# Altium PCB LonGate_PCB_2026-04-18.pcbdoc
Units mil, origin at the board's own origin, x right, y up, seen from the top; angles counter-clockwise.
Board outline 5018.1 x 4750 mil, 2 copper layers (Top Layer, Bottom Layer); 82 components, 100 nets, 301 pads, 185 vias.
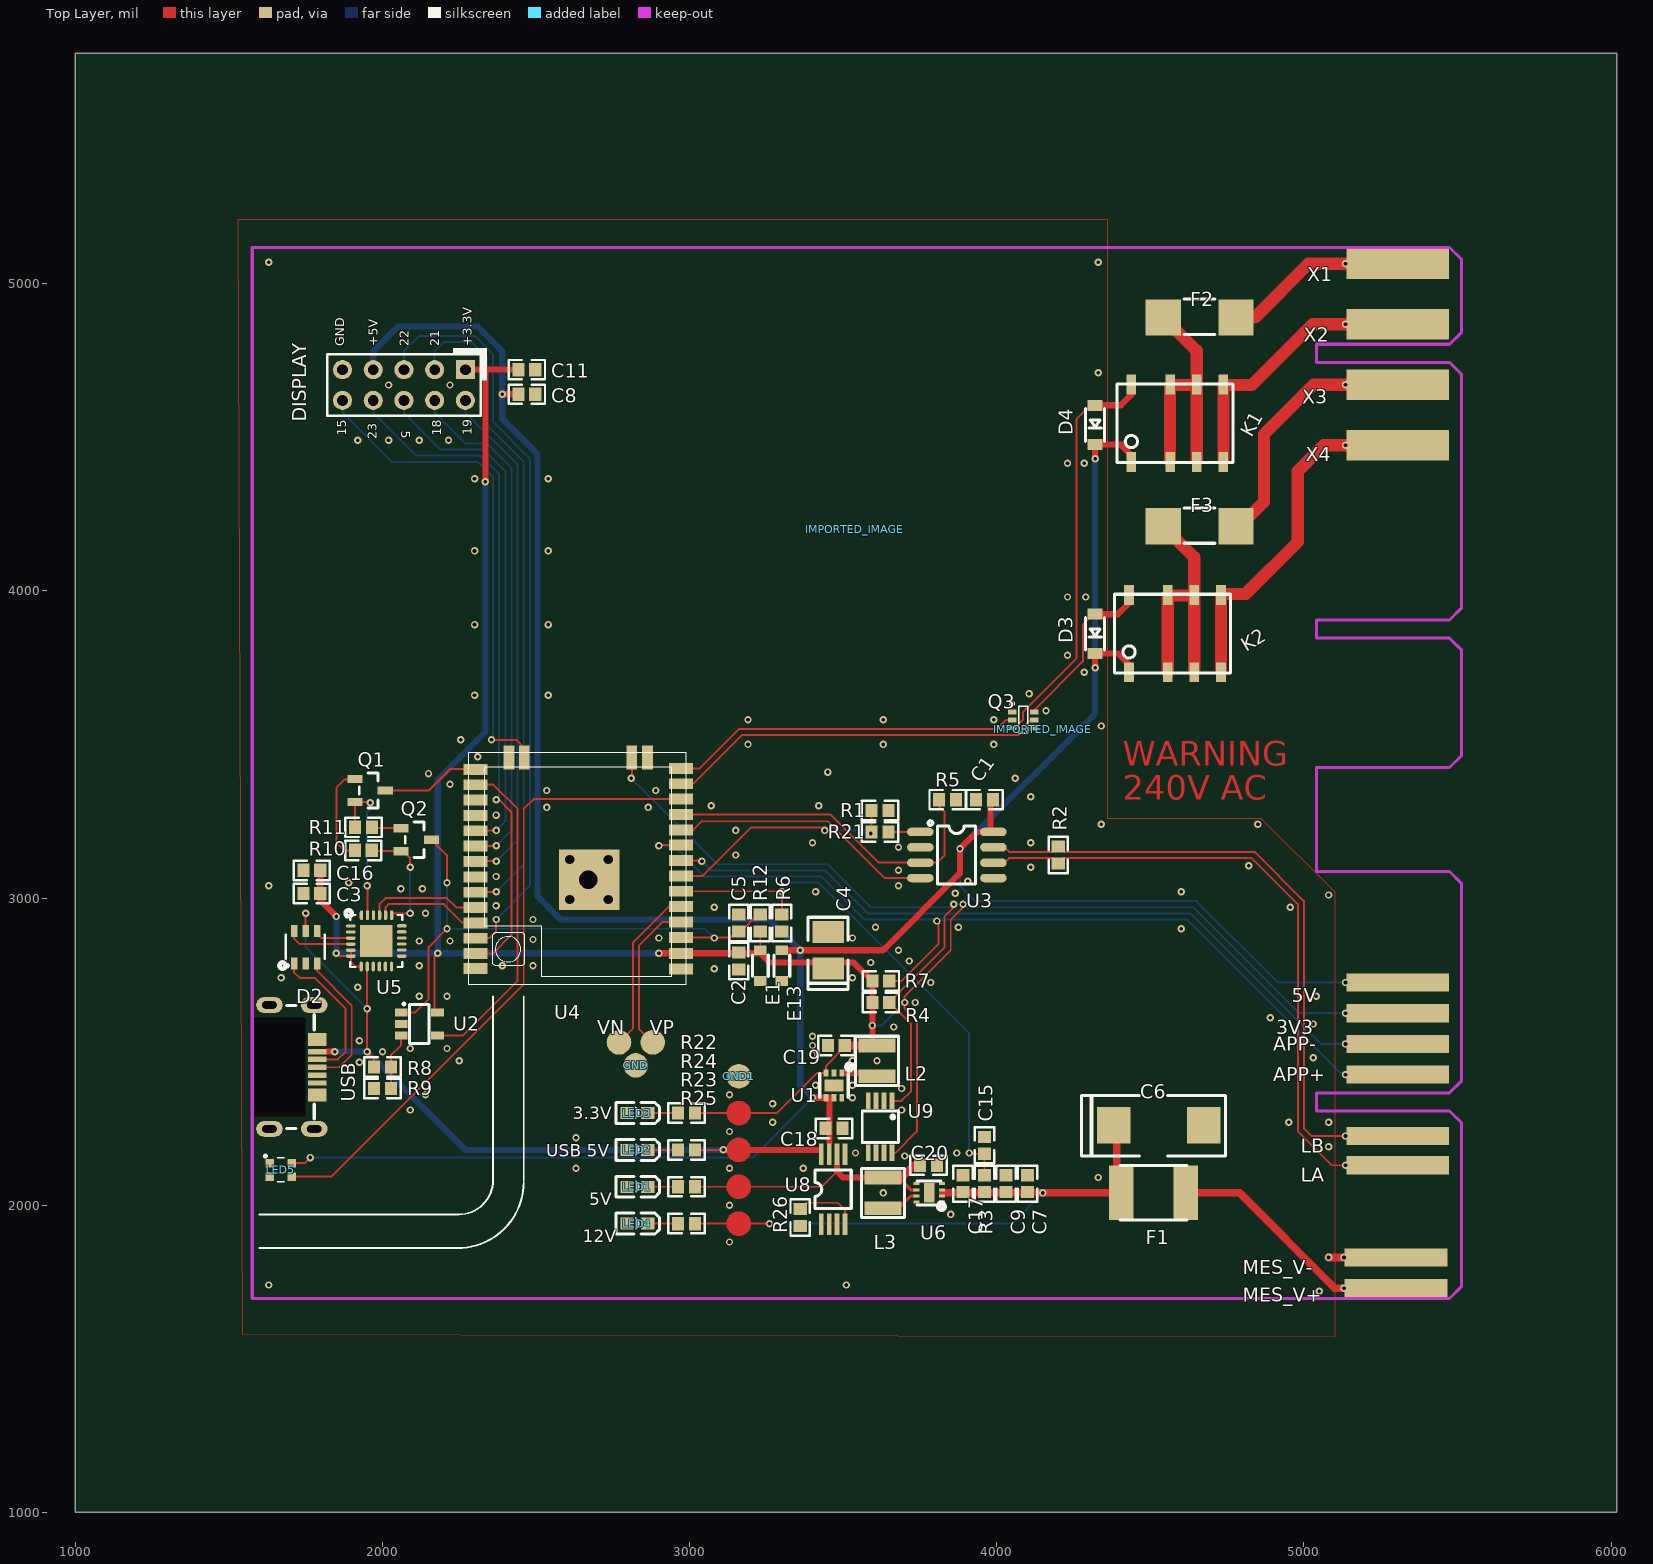
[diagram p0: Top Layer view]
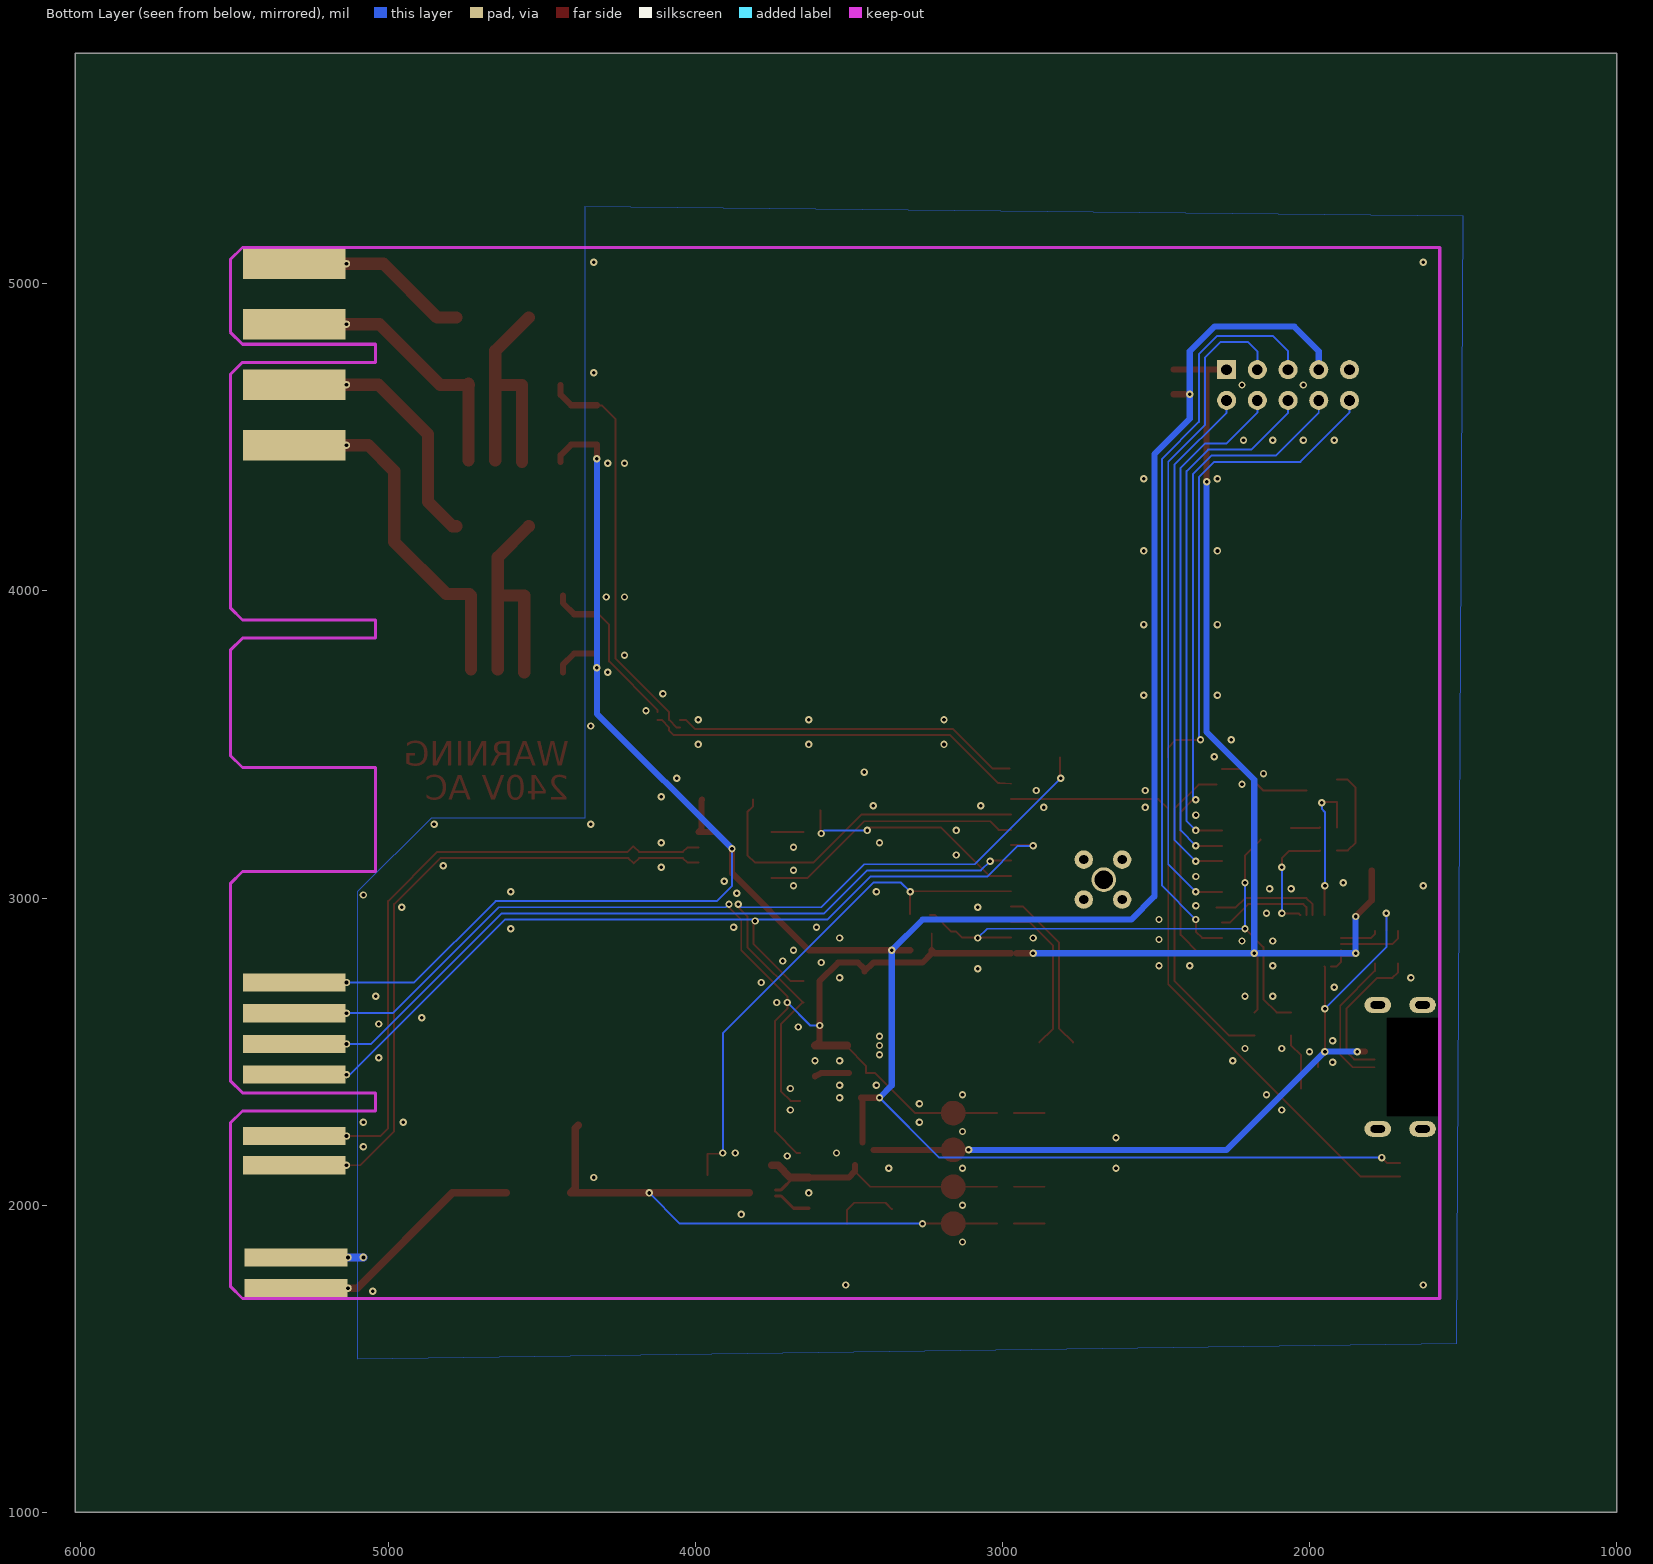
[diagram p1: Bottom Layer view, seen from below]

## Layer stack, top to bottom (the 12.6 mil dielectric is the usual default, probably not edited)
Top Layer: signal copper (thickness not stored)
Dielectric: dielectric 12.6, FR-4, Dk 4.8
Bottom Layer: signal copper (thickness not stored)

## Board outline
6018.1,1000 1000,1000 1000,5750 6018.1,5750

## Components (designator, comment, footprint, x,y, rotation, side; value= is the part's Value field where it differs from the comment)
3V3 "Pad" PAD 5135,2625 r0 top
5V "Pad" PAD 5135,2725 r0 top
APP+ "Pad" PAD 5135,2425 r0 top
APP- "Pad" PAD 5135,2525 r0 top
C1 "100n" 0603#1 3960,3320 r180 top
C2 "10u" 0603#1 3160,2795 r270 top
C3 "10u" 0603#1 1770,3015 r0 top
C4 "220uF" CASE-B_3528 3450.9,2830 r270 top
C5 "1uF" 0603#2 3160,2950 r270 top
C6 "220uF" CAP-SMD_L7.3-W4.3 4527,2260 r0 top
C7 "100nF" 0603#1 4100,2070 r270 top
C8 "100n" 0603#1 2470,4640 r0 top
C9 "100nF" 0603#1 4030,2070 r270 top
C11 "10u" 0603#1 2470,4720 r0 top
C15 "100n" 0603#1 3960,2195 r90 top
C16 "100n" 0603#1 1770,3090 r180 top
C17 "10u" 0603#1 3890,2070.01 r90 top
C18 "10u" 0603#1 3470,2250 r0 top
C19 "10u" 0603#2 3446.06,2520 r0 top
C20 "10u" 0603#2 3809.05,2130 r180 top
D2 "USBLC6-2SC6" SOT-23-6 1750,2840 r90 top
D3 "SS0520" SOD-123 4320,3860 r90 top
D4 "SS0520" SOD-123 4320,4540 r90 top
DISPLAY "Header" HDR-5X2/2.54 2070,4670 r180 top
E1 "UDD32C05L01" SOD-323-BI 3230,2780 r270 top
E13 "UDD32C05L01" SOD-323-BI 3300,2780 r90 top
F1 "2016L150DR" F-SMD2016 4510,2040 r180 top
F2 "SCT1.0A" F-SMD-6.1X2.6 4660,4890 r0 top
F3 "SCT1.0A" F-SMD-6.1X2.6 4660,4210 r0 top
GND "Pad" ROUND_PAD 2825,2455 r0 top
GND1 "Pad" ROUND_PAD 3160,2420 r0 top
IMPORTED_IMAGE "IMPORTED_IMAGE" IMPORTED_IMAGE 3537.17,4200 r0 top
IMPORTED_IMAGE "IMPORTED_IMAGE" IMPORTED_IMAGE 4150,3550.01 r0 top
K1 "HFD4/5-S" HFD4/5-S1R 4587.7,4546 r0 top
K2 "HFD4/3-S" HFD4/5-S1R 4580.01,3861 r0 top
L2 "2.2u" LPS3015-223MRB 3610,2470 r90 top
L3 "2.2u" LPS3015-223MRB 3630,2040 r90 top
LA "Pad" PAD 5135,2130 r0 top
LB "Pad" PAD 5135,2225 r0 top
LED1 "LED green" LED-0603F 2830,2060 r180 top
LED2 "LED blue" LED-0603F 2830,2180 r180 top
LED3 "LED red" LED-0603F 2830,2300 r180 top
LED4 "LED orange" LED-0603F 2830,1940 r180 top
LED5 "STATUS" LED_WS2812-2020_FL 1670,2130 r180 top
MES_V+ "Pad" PAD 5130,1730 r0 top
MES_V- "Y14" PAD 5130,1830 r0 top
Q1 "MMBT2222A" SOT-23(SOT-23-3) 2010,3350 r270 top
Q2 "MMBT2222A" SOT-23(SOT-23-3) 2160,3190 r270 top
Q3 "MUN5233DW1T1G" SOT-363 4086,3579.8 r270 top
R1 "2k2" 0603#1 3620,3285 r0 top
R2 "1k" 0603#1 4200,3140 r90 top
R3 "8k2" 0603#1 3960,2070 r270 top
R4 "2k2" 0603#1 3622.44,2660 r180 top
R5 "10k" 0603#1 3840,3320 r180 top
R6 "2k2" 0603#1 3300,2918.5 r90 top
R7 "1k" 0603#1 3622.44,2730 r180 top
R8 "1k" 0603#1 2000,2450 r0 top
R9 "2k2" 0603#1 2000,2380 r0 top
R10 "10k" 0603#2 1906.06,3155 r0 top
R11 "10k" 0603#2 1970,3230 r180 top
R12 "10k" 0603#2 3230,2950 r270 top
R21 "1k" 0603#1 3620,3215 r180 top
R22 "1k" 0603#1 2990,2300 r0 top
R23 "1k" 0603#1 2990,2060 r0 top
R24 "1k" 0603#1 2990,2180 r0 top
R25 "10k" 0603#1 2990,1940 r0 top
R26 "250" 0603#1 3360,1960 r270 top
U1 "TPS62291DRVR" SON-6-EP-2X2MM 3469.6,2390 r270 top
U2 "STWD100NYWY3F" SOT-23-5 2120,2590 r0 top
U3 "MAX1487CSA+T" SOIC-8_150MIL 3870,3140 r0 top
U4 "ESP32-WROOM/WROVER" ESP32-WROOM-32U 3090,2670 r180 top
U5 "CP2104-F03-GM" QFN-24_4X4X05P 1905,2905 r0 top
U6 "TPS62163DSG" WSON-8-PAD 3780,2040 r90 top
U8 "TPS2113APWR" TSSOP-8 3467,2052 r90 top
U9 "DS18B20U+T&R" USOP-8 3620,2255 r180 top
USB "MICRO_USB" MICRO_5P_C40940 1710,2450 r270 top
VN "Pad" ROUND_PAD 2770,2530 r0 top
VP "Pad" ROUND_PAD 2880,2530 r0 top
X1 "Pad" PAD-2.54 5135,5065 r0 top
X2 "Pad" PAD-2.54 5135,4868 r0 top
X3 "Pad" PAD-2.54 5135,4671 r0 top
X4 "Pad" PAD-2.54 5135,4474 r0 top

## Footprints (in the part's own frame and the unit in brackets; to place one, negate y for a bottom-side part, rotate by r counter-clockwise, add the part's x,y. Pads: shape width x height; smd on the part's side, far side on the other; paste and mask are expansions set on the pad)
0603#1 [mm]
  rect 1x1.1 smd paste+0 mask+0.102: 1(-0.7,0) 2(0.7,0)
  silkscreen extent -1.5,-0.8 1.5,0.8
0603#2 [mm]
  rect 1x1.1 smd paste+0 mask+0.102: 1(0.1,0) 2(1.5,0)
  silkscreen extent -0.7,-0.8 2.3,0.8
CAP-SMD_L7.3-W4.3 [mil]
  rect 110.2x118.5 smd paste+0 mask+4: 1(-146.5,0) 2(146.5,0)
  silkscreen extent -252,-100 218,97
CASE-B_3528 [mm]
  rect 1.8x2.6 smd paste+0 mask+0.102: 1(1.501,0) 2(-1.501,0)
  silkscreen extent -2.73,-1.65 3.26,1.65
ESP32-WROOM-32U [mm]
  rect 2x0.9 smd paste+0 mask+0.102: 1(3,-2.5) 2(3,-3.8) 3(3.002,-5.102) 4(3,-6.4) 5(3,-7.67) 6(3,-8.94) 7(3,-10.21) 8(3,-11.48) 9(3,-12.75) 10(3,-14.02) 11(3,-15.29) 12(3,-16.56) 13(3,-17.83) 14(3,-19.1) 25(20.002,-19.022) 26(20.002,-17.752) 27(20.002,-16.482) 28(20.002,-15.212) 29(20.002,-13.942) 30(20.002,-12.672) 31(20.002,-11.402) 32(20.002,-10.132) 33(20.001,-8.862) 34(20.002,-7.592) 35(20.002,-6.322) 36(20.002,-5.052) 37(20.002,-3.782) 38(20,-2.54)
  rect 0.9x2 smd paste+0 mask+0.102: 15(5.772,-20.001) 16(7.069,-20.001) 23(15.959,-20.001) 24(17.229,-20.001)
  rect 5x5 smd paste+0 mask+0.102: 39(10.602,-9.901)
  silkscreen extent 2.56,-20.4 20.56,-1.2
F-SMD2016 [mm]
  rect 2x4.5 smd paste+0 mask+0.102: 1(-2.667,0) 2(2.667,0)
  silkscreen extent -2.75,-2.25 2.75,2.25
F-SMD-6.1X2.6 [mm]
  rect 2.9x3 smd paste+0 mask+0.102: 1(-3,0) 2(3,0)
  silkscreen extent -1.27,-1.4 1.27,1.52
HDR-5X2/2.54 [mil]
  rect 62x62 hole 35 paste+0 mask+4: 1(-200,-50)
  round 62 hole 35 paste+0 mask+4: 2(-200,50) 3(-100,-50) 4(-100,50) 5(0,-50) 6(0,50) 7(100,-50) 8(100,50) 9(200,-50) 10(200,50)
  silkscreen extent -250,-100 250,100
HFD4/5-S1R [mm]
  rect 0.8x1.65 smd paste+0 mask+0.102: 1(-3.8,-3.2) 2(-0.6,-3.2) 3(1.6,-3.2) 4(3.8,-3.2) 5(3.8,3.2) 6(1.6,3.2) 7(-0.6,3.2) 8(-3.8,3.2)
  silkscreen extent -5,-3.25 4.6,3.25
IMPORTED_IMAGE [mil]
LED-0603F [mil]
  rect 43x39 smd paste+0 mask+4: 1(-33.5,0) 2(33.5,0)
  silkscreen extent -72,-34 70,34
LED_WS2812-2020_FL [mil]
  rect 27.56x27.56 smd paste+0 mask+4: 1(36.92,-6.66) 2(36.92,36.65) 3(-35.13,36.65) 4(-35.13,-6.66)
  silkscreen extent -11,-34 55,54
LPS3015-223MRB [mil]
  rect 44.9x120.1 smd paste+0 mask+4: P$1(-50,0) P$2(50,0)
  silkscreen extent -80,-70 80,70
MICRO_5P_C40940 [mm]
  rect 0.45x1.5 smd paste+0 mask+0.102: 1(-1.276,1.975) 2(-0.626,1.975) 3(0.025,1.975) 4(0.675,1.975) 5(1.325,1.975)
  oval 1.3x2.2 hole 0.6 slot 1.2 at 90 deg paste+0 mask+0.102: 5(-5.125,1.725) 5(-5.125,-1.975) 5(5.125,1.725) 5(5.125,-1.975)
  rect 1.1x1.5 smd paste+0 mask+0.102: ""(-2.275,1.975) ""(2.325,1.975)
  Multi-Layer board cut-out: -4.064,0.963 4.064,0.963 4.064,-3.355 -4.064,-3.355
  silkscreen extent -5.08,-0.56 5.08,1.73
PAD [mm]
  round 0.61 hole 0.305 paste+0 mask+0.102: 1(0,0)
  rect 8.5x1.5 smd far side paste+0 mask+0.102: 1(4.318,0)
  rect 8.5x1.5 smd paste+0 mask+0.102: 1(4.318,0)
PAD-2.54 [mm]
  round 0.61 hole 0.305 paste+0 mask+0.102: 1(0,0)
  rect 8.5x2.54 smd far side paste+0 mask+0.102: 1(4.318,0)
  rect 8.5x2.54 smd paste+0 mask+0.102: 1(4.318,0)
QFN-24_4X4X05P [mm]
  oval 0.8x0.28 smd paste+0 mask+0.102: 1(-0.203,0.102) 2(-0.203,-0.399) 3(-0.203,-0.899) 4(-0.203,-1.397) 5(-0.203,-1.897) 6(-0.203,-2.398) 13(4.013,-2.388) 14(4.013,-1.887) 15(4.013,-1.387) 16(4.013,-0.889) 17(4.013,-0.389) 18(4.013,0.112)
  oval 0.28x0.8 smd paste+0 mask+0.102: 7(0.66,-3.251) 8(1.161,-3.251) 9(1.661,-3.251) 10(2.159,-3.251) 11(2.659,-3.251) 12(3.16,-3.251) 19(3.175,0.991) 20(2.675,0.991) 21(2.174,0.991) 22(1.676,0.991) 23(1.176,0.991) 24(0.676,0.991)
  rect 2.68x2.68 smd paste+0 mask+0.102: 25(1.905,-1.143)
  silkscreen extent -0.57,-3.29 4.06,1.01
ROUND_PAD [mil]
  round 80 smd paste+0 mask+4: 1(0,0)
SOD-123 [mil]
  rect 35.8x48 smd paste+0 mask+4: 1(64,0) 2(-64,0)
  silkscreen extent -53,-31 53,31
SOD-323-BI [mm]
  rect 0.8x1 smd paste+0 mask+0.102: 1(-1.27,0) 2(1.27,0)
  silkscreen extent -0.89,-0.66 0.89,0.66
SOIC-8_150MIL [mm]
  oval 2.2x0.7 smd paste+0 mask+0.102: 1(-3.023,1.905) 2(-3.023,0.635) 3(-3.023,-0.635) 4(-3.023,-1.905) 5(3.023,-1.905) 6(3.023,-0.635) 7(3.023,0.635) 8(3.023,1.905)
  silkscreen extent -2.37,-2.41 1.55,2.83
SON-6-EP-2X2MM [mm]
  rect 0.6x0.4 smd paste+0 mask+0.102: 1(-1.016,0.65) 2(-1.016,0) 3(-1.016,-0.65) 4(1.016,-0.65) 5(1.016,0) 6(1.016,0.65)
  rect 1x1.6 smd paste+0 mask+0.102: 7(0,0.01)
  silkscreen extent -1.62,-1.17 1,1.33
SOT-23(SOT-23-3) [mm]
  rect 0.7x1.25 smd paste+0 mask+0.102: 1(-0.95,-2.52) 2(0.95,-2.52) 3(0,-0.02)
  silkscreen extent -1.46,-2.17 1.46,-0.62
SOT-23-5 [mm]
  rect 1.06x0.65 smd paste+0 mask+0.102: 1(-1.5,0.95) 2(-1.5,0) 3(-1.5,-0.95) 4(1.5,-0.95) 5(1.5,0.95)
  silkscreen extent -1.33,-1.6 0.8,1.71
SOT-23-6 [mm]
  rect 1x0.55 smd paste+0 mask+0.102: 1(-1.35,0.95) 2(-1.35,0) 3(-1.35,-0.95) 4(1.35,-0.95) 5(1.35,0) 6(1.35,0.95)
  silkscreen extent -1.67,-1.56 1.01,1.67
SOT-363 [mil]
  rect 15.75x27.6 smd paste+0 mask+4: 1(-25.8,-36) 2(-0.2,-36) 3(25.4,-36) 4(25.8,36) 5(0.2,36) 6(-25.4,36)
  silkscreen extent -58,-42 44,15
TSSOP-8 [mil]
  rect 71x16 smd paste+0 mask+4: 1(-114,38.5) 2(-114,12.5) 3(-114,-12.5) 4(-114,-38.5) 5(114,-38.5) 6(114,-12.5) 7(114,12.5) 8(114,38.5)
  silkscreen extent -63,-59 63,60
USOP-8 [mm]
  rect 0.4x1.349 smd paste+0 mask+0.102: 1(-0.975,-2.15) 2(-0.325,-2.152) 3(0.325,-2.151) 4(0.975,-2.152) 5(0.976,2.149) 6(0.324,2.152) 7(-0.324,2.149) 8(-0.976,2.152)
  silkscreen extent -1.52,-1.3 1.48,1.3
WSON-8-PAD [mil]
  rect 10x19.7 smd paste+0 mask+4: 1(-30,-41) 2(-10,-41) 3(10,-41) 4(30,-41) 5(30,41) 6(10,41) 7(-10,41) 8(-30,41)
  rect 63x35.4 smd paste+0 mask+4: 9(0,0)
  silkscreen extent -49,-49 39,39

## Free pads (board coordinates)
  round 60 hole 30 paste+0 mask+4: 1(2610,2995) 1(2610,3125) 1(2735,2995) 1(2735,3125)
  round 80 hole 60 paste+0 mask+4: 1(2670,3060)

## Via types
v1: diameter 24, hole 12, Top Layer to Bottom Layer, tented both sides, 143 vias
v2: diameter 24.02, hole 12.2, Top Layer to Bottom Layer, tented both sides, 42 vias

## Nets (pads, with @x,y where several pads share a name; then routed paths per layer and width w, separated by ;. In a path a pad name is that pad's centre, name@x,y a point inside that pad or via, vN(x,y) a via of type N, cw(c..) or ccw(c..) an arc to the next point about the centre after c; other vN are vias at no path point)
+5V: C20.2 L3.P$2 R23.2 U6.6 U8.6 | length 1049.2
  Top Layer w6.3: R23.2 3430,2060 3480,2110
  Top Layer w10: L3.P$2@3625,2090 3680,2090 3720,2050 U6.6
  Top Layer w20: 3480,2130 3480,2110 3500,2090 L3.P$2@3625,2090
  Top Layer w25: L3.P$2 3690,2090 3730,2130 C20.2
  Top Layer w40: 3180,2060 ccw(c3160,2060) 3180,2060
ADC: C15.1 R3.1 R6.2 U4.6 | length 1737.7
  Top Layer w6.3: U4.6 3298.03,3021.97 v1(3300,3020) R6.2@3300,2947.55 ; v1(3910,2170) 3912.56,2167.44 C15.1 R3.1
  Bottom Layer w6.3: v1(3300,3020) 3330,3050 3420,3050 3910,2560 v1(3910,2170)
APP+: APP+.1 R7.1 U4.9 | length 2905.5
  Top Layer w6.3: v1(2900,3170) 2901.97,3171.97 U4.9 ; R7.1@3647.6,2730 3690,2730 3810,2850 3810,2920 v1(3805,2925)
  Bottom Layer w6.3: v1(2900,3170) 2950,3170 3050,3070 3430,3070 3570,2930 4620,2930 5125,2425 APP+.1@5135,2425
APP-: APP-.1 U4.8 | length 2410.4
  Top Layer w6.3: U4.8 3038.03,3121.97 v1(3040,3120)
  Bottom Layer w6.3: v1(3040,3120) 3070,3090 3440,3090 3580,2950 4630,2950 5055,2525 APP-.1@5135,2525
D+: D2.3 USB.3 | length 472.6
  Top Layer w6.3: D2.3 1787.4,2762.6 1900,2650 1900,2490 1859.01,2449.01 USB.3
D+P: D2.4 U5.3 | length 125.5
  Top Layer w6.3: D2.4 1787.4,2882.6 1800.4,2869.6 U5.3
D-: D2.1 USB.2 | length 488.2
  Top Layer w6.3: D2.1 1712.6,2757.4 1730,2740 1780,2740 1880,2640 1880,2500 1854.63,2474.63 USB.2
D-P: D2.6 U5.4 | length 217.3
  Top Layer w6.3: D2.6 1712.6,2867.4 1730,2850 U5.4
DISP_2: DISPLAY.2 U4.31 | length 1683.7
  Top Layer w6.3: U4.31@2285.67,3120 v1(2370,3120)
  Bottom Layer w6.3: DISPLAY.2 2270,4580 2440,4410 2440,3190 v1(2370,3120)
DISP_3: DISPLAY.3 U4.33 | length 2174.5
  Top Layer w6.3: U4.33@2285.67,3020 v1(2370,3020)
  Bottom Layer w6.3: DISPLAY.3 2170,4780 2200,4810 2290,4810 2340,4760 2340,4540 2460,4420 2460,3110 v1(2370,3020)
DISP_4: DISPLAY.4 U4.30 | length 1699.6
  Top Layer w6.3: U4.30@2285.7,3170 v1(2370,3170)
  Bottom Layer w6.3: DISPLAY.4 2170,4580 2270,4480 2340,4480 2420,4400 2420,3220 v1(2370,3170)
DISP_5: DISPLAY.5 U4.36 | length 2463.4
  Top Layer w6.3: U4.36@2285.7,2870 2350,2870 2370,2890 v1(2370,2930)
  Bottom Layer w6.3: DISPLAY.5 2070,4780 2120,4830 2300,4830 2360,4770 2360,4550 2480,4430 2480,3040 v1(2370,2930)
DISP_6: DISPLAY.6 U4.29 | length 1715.5
  Top Layer w6.3: U4.29@2285.67,3220 v1(2370,3220)
  Bottom Layer w6.3: DISPLAY.6 2070,4580 2190,4460 2330,4460 2400,4390 2400,3250 v1(2370,3220)
DISP_8: DISPLAY.8 U4.37 | length 2206.4
  Top Layer w6.3: U4.37 2358.9,2818.9 2420,2880 2420,3280 2380,3320 v1(2370,3320)
  Bottom Layer w6.3: DISPLAY.8 1970,4580 2110,4440 2320,4440 2380,4380 2380,3330 v1(2370,3320)
DISP_10: DISPLAY.10 U4.23 | length 1622.7
  Top Layer w6.3: v1(2355,3515) 2435,3515 2461.7,3488.3 U4.23
  Bottom Layer w6.3: DISPLAY.10 1870,4580 2030,4420 2310,4420 2360,4370 2360,3520 v1(2355,3515)
DTR: Q1.2 R11.2 U5.23 | length 503.4
  Top Layer w6.3: Q1.2 Q1.2@1910.95,3312.45 ; R11.2@1910.95,3230 Q1.2@1910.95,3312.45 ; v1(1950,3040) 1951.3,3038.7 U5.23 ; v1(1960,3310) 1957.55,3312.45 Q1.2@1910.95,3312.45
  Bottom Layer w6.3: v1(1950,3040) 1950,3280 1960,3290 v1(1960,3310)
GND: C1.2 C2.2 C3.1 C4.2 C5.1 C6.2 C7.1 C8.2 C9.1 C11.2 C15.2 C16.2 C17.2 C18.2 C19.1 C20.1 D2.2 DISPLAY.9 E1.2 E13.1 GND1.1 GND.1 LED1.2 LED2.2 LED3.2 LED4.2 LED5.2 MES_V-.1 pad.1 Q3.1 Q3.4 R1.2 R5.1 R6.1 R9.1 R26.2 U1.2 U1.6 U1.7 U2.2 U3.2 U3.5 U4.1 U4.15 U4.24 U4.38 U4.39 U5.2 U6.1 U6.4 U6.5 U6.9 U8.2 U8.3 U8.5 U9.4 USB.5 | length 100
  Top Layer w25: v1(5080,1830) MES_V-.1@5130,1830
  Bottom Layer w25: v1(5080,1830) MES_V-.1@5130,1830
  other v1: 5050,1720 1630,1740 3510,1740 3130,1880 3850,1970 3130,2000 3630,2040 4330,2090 2630,2120 3130,2120 3370,2120 3700,2160 3540,2170 3870,2170 5080,2190 2630,2220 3130,2240 3270,2270 4950,2270 5080,2270 2090,2310 3690,2310 3270,2330 3530,2350 2140,2360 3130,2360 3690,2380 3410,2390 3530,2390 1925,2465 3530,2470 3610,2470 5030,2480 3400,2490 2000,2500 2090,2510 2210,2510 3400,2520 1925,2535 3400,2550 3665,2580 5030,2590 4890,2610 3735,2660 2120,2680 5040,2680 1920,2710 3785,2725 1670,2740 3530,2740 3080,2770 2120,2780 2390,2780 2490,2780 3590,2790 3715,2795 3680,2830 2900,2870 3530,2870 4600,2900 3605,2905 3875,2905 3080,2970 4955,2970 5080,3010 3865,3015 4600,3020 1630,3040 3905,3055 4110,3100 4820,3105 3150,3140 3400,3180 4110,3180 3150,3220 4340,3240 4850,3240 4110,3330 4060,3390 3450,3410 3190,3500 3630,3500 3990,3500 4340,3560 3190,3580 3630,3580 3990,3580 4160,3610 4105,3665 4285,3735 4230,3790 4230,3980 4290,3980 4230,4415 4285,4415 4330,4710 1630,5070 4330,5070
  other v2: 2250,2470 2210,2680 2120,2860 2220,2860 2490,2865 2490,2930 2140,2950 2370,2975 3410,3020 2060,3030 2130,3030 3680,3040 1890,3050 2370,3070 3680,3090 3680,3165 2370,3270 2535,3295 2865,3295 3070,3300 3420,3300 2535,3350 2890,3350 2220,3370 2150,3405 2310,3460 2255,3515 2300,3660 2540,3660 2300,3890 2540,3890 2300,4130 2540,4130 2300,4365 2540,4365 1920,4490 2020,4490 2120,4490 2215,4490 2020,4670 2220,4670
IO0: Q1.3 U4.25 | length 305.5
  Top Layer w6.3: Q1.3 2150,3350 2220,3420 U4.25@2285.7,3420
K1_2: F2.1 K1.2 K1.3 K1.6 K1.7 | length 851.7
  Top Layer w40: F2.1 4650.7,4781.19 4650.7,4670 4564.09,4670 K1.2 ; K1.3@4651.1,4425 K1.6@4651.1,4675
K1_4: K1.4 K1.5 X2.1 | length 729.7
  Top Layer w40: K1.5@4737.32,4670 4830,4670 5028,4868 X2.1@5135,4868 ; K1.4@4737.71,4425 K1.5@4737.71,4675
K1_8: D4.1 K1.8 Q3.3 | length 1340.4
  Top Layer w6.3: Q3.3 4059.4,3554.4 4085,3580 4085,3605 4260,3780 4260,4560 4304,4604 D4.1
  Top Layer w20: D4.1 4404,4604 4438.1,4638.1 K1.8@4438.1,4670
K2_2: F3.1 K2.2 K2.3 K2.6 K2.7 | length 843.5
  Top Layer w40: F3.1 4642.99,4108.9 K2.6@4642.99,3985 ; K2.2 4556.38,3985 K2.6@4642.99,3985 ; K2.3@4642.99,3745 K2.6@4642.99,3985
K2_4: K2.4 K2.5 X4.1 | length 1145.6
  Top Layer w40: K2.4@4729.6,3745 K2.5@4729.6,3985 ; K2.5@4734.6,3990 4810,3990 4980,4160 4980,4390 5064,4474 X4.1@5305,4474
K2_8: D3.1 K2.8 Q3.6 | length 554.4
  Top Layer w6.3: Q3.6 4122,3612 4280,3770 4280,3890 4314,3924 D3.1
  Top Layer w20: D3.1 4394,3924 4430.4,3960.4 K2.8@4430.4,3985
L2_P$1: L2.P$1 U1.1 | length 112.4
  Top Layer w20: U1.1@3500,2430 3590,2430 L2.P$1
LED1_1: LED1.1 R23.1 | length 98.9
  Top Layer w6.3: LED1.1 R23.1
LED2_1: LED2.1 R24.1 | length 98.9
  Top Layer w6.3: LED2.1 R24.1
LED3_1: LED3.1 R22.1 | length 98.9
  Top Layer w6.3: LED3.1 R22.1
LED5_1: LED5.1
LON_DE: R5.2 U3.3 U4.11 | length 1120.7
  Top Layer w6.3: U4.11 3458.03,3271.97 3615,3115 U3.3 3805,3115 3830,3140 3830,3280 3812.5,3297.5 R5.2@3812.5,3320
LON_DI: U3.4 U4.10 | length 867.3
  Top Layer w6.3: U4.10 3012,3222 3040,3250 3450,3250 3635,3065 U3.4
LON_RO: R1.1 R21.2 U4.7 | length 761.8
  Top Layer w6.3: U4.7 3042,3072 3200,3230 3430,3230 v1(3440,3220) ; R21.2@3592.45,3215 R1.1@3592.45,3284.99
  Bottom Layer w6.3: v1(3440,3220) 3580,3220 v1(3590,3210)
R2_1: LA.1 R2.1 U3.6 | length 2014.5
  Top Layer w6.3: U3.6 4025,3115 4040,3130 4182.44,3130 R2.1 ; R2.1 4217.6,3130 4830,3130 4980,2980 4980,2240 5090,2130 LA.1@5135,2130
R2_2: LB.1 R2.2 U3.7 | length 1983.4
  Top Layer w6.3: U3.7 4025,3165 4040,3150 4182.45,3150 R2.2 ; R2.2@4200,3167.5 4202.5,3167.5 4220,3150 4840,3150 5000,2990 5000,2250 5025,2225 LB.1@5135,2225
R10_1: Q1.1 R10.1 | length 322.4
  Top Layer w6.3: R10.1@1909.6,3153.8 R10.1 1875,3155 1850,3180 1850,3359.2 1877,3386.2 Q1.1@1910.4,3386.2
R11_1: Q2.1 R11.1 | length 95.8
  Top Layer w6.3: R11.1 1968.66,3227.4 Q2.1
R25_1: LED4.1 R25.1 | length 98.9
  Top Layer w6.3: LED4.1 R25.1
REL1: Q3.5 U4.13 | length 1250.7
  Top Layer w6.3: U4.13 3010,3375 3015,3375 3170,3530 4070,3530 4085,3545 4085,3555 4109.6,3579.6 Q3.5 Q3.5@4112.1,3579.6
REL2: Q3.2 U4.14 | length 1139.9
  Top Layer w6.3: U4.14@2976,3421 3031,3421 3160,3550 4000,3550 4030,3580 Q3.2
RESET: C5.2 Q2.3 R12.1 U2.1 U4.3 | length 1848.9
  Top Layer w6.3: U2.1@2061,2627.4 2107.4,2627.4 2150,2670 2150,2840 v1(2210,2900) ; Q2.3 2210,3139.2 v1(2210,3050) ; U4.3 3130.8,2870.8 3150.9,2890.9 C5.2 3165.9,2890.9 3220,2945 R12.1@3235,2945
  Bottom Layer w6.3: v1(2210,3050) v1(2210,2900) 3050,2900 v1(3080,2870)
RTS: Q2.2 R10.2 U5.19 | length 377.7
  Top Layer w6.3: R10.2 1967.52,3152.6 Q2.2 2067.4,3152.6 2090,3130 v1(2090,3100) ; U5.19 2036,2950 v2(2090,2950)
  Bottom Layer w6.3: v2(2090,2950) v1(2090,3100)
RXD0: U4.34 U5.21 | length 369.4
  Top Layer w6.3: U5.21 1990.6,2980.6 2010,3000 2210,3000 2241.1,2968.9 U4.34
S$11: 
S$21: 
S$23: 
S$27: 
S$30: 
S$32: 
S$67: 
S$69: 
S$110: 
S$112: 
S$114: 
S$116: 
S$282: 
S$289: 
S$1042: 
S$1047: 
TEMP_INT: R4.1 U4.16 U9.1 | length 2104.6
  Top Layer w6.3: v1(2810,3390) 2811.7,3388.3 U4.16 ; U9.1@3658.4,2339.7 3689.7,2339.7 3720,2370 3720,2590 R4.1 ; v1(3860,2980) 3860,2970 3830,2940 3830,2840 R4.1 ; R4.1 3647.6,2660 R4.1
  Bottom Layer w6.3: v1(2810,3390) 3090,3110 3450,3110 3590,2970 3850,2970 v1(3860,2980)
TXD0: U4.35 U5.20 | length 330.6
  Top Layer w6.3: U5.20 2010.3,2970.3 2020,2980 2200,2980 2260,2920 U4.35@2285.7,2920
U2_3: R8.2 R9.2 U2.3 | length 186.4
  Top Layer w6.3: R9.2 2027.56,2487.56 2060.95,2520.95 U2.3@2060.95,2552.6
U3_1: R21.1 U3.1 | length 103.4
  Top Layer w6.3: R21.1 3675,3215 U3.1
U4_4: U4.4 VP.1 | length 502.4
  Top Layer w6.3: VP.1 2835,2575 2835,2845 2912,2922 U4.4
U4_5: U4.5 VN.1 | length 549
  Top Layer w6.3: VN.1 2815,2575 2815,2855 2932,2972 U4.5
U4_27: U4.27
U4_28: U4.28
U4_32: U4.32
U5_1: U5.1
U5_9: U5.9
U5_10: U5.10
U5_11: U5.11
U5_12: U5.12
U5_13: U5.13
U5_14: U5.14
U5_15: U5.15
U5_16: U5.16
U5_17: U5.17
U5_18: U5.18
U5_22: U5.22
U5_24: U5.24
U5_25: U5.25
U6_7: L3.P$1 U6.7 | length 125.6
  Top Layer w10: L3.P$1 3680,1990 3720,2030 U6.7
U6_8: U6.8
U8_1: U8.1
U8_4: R26.1 U8.4 | length 210.2
  Top Layer w6.3: R26.1 3380.44,2008 3482,2008 3505.5,1984.5 U8.4
U9_2: U9.2
U9_3: U9.3
U9_5: U9.5
U9_6: U9.6
U9_7: U9.7
USB_4: USB.4
VCC: 3V3.1 C2.1 C3.2 C4.1 C11.1 C16.1 C19.2 DISPLAY.1 E1.1 L2.P$2 R4.2 R7.2 R12.2 R22.2 U1.3 U2.5 U4.2 U5.5 U5.6 U5.7 U9.8 | length 8185.7
  Top Layer w6.3: v1(1850,2820) 1859.4,2810.6 U5.6 ; U5.5 1897,2820.3 U5.6 ; U5.7 1913,2777 1897,2793 U5.6 ; U2.5 2170,2636.4 2170,2810 v1(2180,2820) ; R22.2 3284,2300 3414,2430 U1.3 3444,2454 3505.11,2515.11 C19.2 ; E1.1@3230,2835 R12.2@3230,2884.9 ; U9.8 3670.3,2170.3 3740,2240 3740,2600 3700,2640 v1(3700,2660) 3700,2680 3850,2830 3850,2930 3890,2970 v1(3890,2980)
  Top Layer w20: C16.1 1797.56,2992.44 v1(1850,2940) ; v1(2335,4355) 2335,4720 DISPLAY.1 C11.1 ; v1(2900,2820) U4.2@2954.33,2820 ; U4.2@2971.9,2820 3220,2820 E1.1 3230,2820 3260,2790 3420,2790 C4.1@3449.1,2760.9 ; C4.1 3470,2790 3534.9,2790 R7.2 3594.89,2535.11 L2.P$2
  Top Layer w25: C19.2 3537.2,2520 L2.P$2
  Top Layer w40: 3180,2300 ccw(c3160,2300) 3180,2300
  Bottom Layer w6.3: v1(3595,2585) 3625,2585 v1(3700,2660) ; v1(3890,2980) 3900,2970 4640,2970 4985,2625 3V3.1@5135,2625
  Bottom Layer w20: v1(1850,2940) v1(1850,2820) v1(2900,2820) ; v1(2180,2820) 2180,3385 2335,3540 v1(2335,4355)
VCC5: 5V.1 C1.1 C8.1 C18.1 D3.2 D4.2 DISPLAY.7 E13.2 K1.1 K2.1 LED5.4 U1.4 U1.5 U3.8 U8.7 | length 10193.7
  Top Layer w6.3: LED5.4 1746.7,2136.7 v1(1765,2155)
  Top Layer w20: v1(2390,4640) C8.1 ; E13.2 v1(3360,2830) 3630,2830 3880,3080 v1(3880,3160) 3935,3215 U3.8 3980,3224 3980,3317.56 C1.1@3977.56,3320 ; v1(3400,2350) 3460,2350 ; 3455,2204 3455,2350 ; v1(4320,3750) D3.2 4394,3796 4430.4,3759.6 K2.1 ; v1(4320,4430) D4.2 4404,4476 4438.1,4441.9 K1.1
  Bottom Layer w6.3: v1(1765,2155) 3205,2155 v1(3400,2350) ; v1(3880,3160) 3880,3040 3930,2990 4650,2990 4915,2725 5V.1@5135,2725
  Bottom Layer w20: DISPLAY.7 1970,4780 2050,4860 2310,4860 2390,4780 2390,4560 2505,4445 2505,3005 2580,2930 3260,2930 v1(3360,2830) 3360,2390 v1(3400,2350) ; v1(3880,3160) 4320,3600 v1(4320,3750) v1(4320,4430)
VIN: F1.1 MES_V+.1 | length 643.4
  Top Layer w25: F1.1 4790,2040 5100,1730 MES_V+.1@5130,1730
VIN_F: C6.1 C7.2 C9.2 C17.1 F1.2 R3.2 R25.2 U6.2 U6.3 | length 2109.7
  Top Layer w6.3: R25.2 v1(3260,1940)
  Top Layer w25: 3825,2040 3950,2040 F1.2 4390,2055 4390,2250.5 C6.1
  Top Layer w40: 3180,1940 ccw(c3160,1940) 3180,1940
  Bottom Layer w6.3: v1(3260,1940) 4050,1940 v1(4150,2040)
VUSB: D2.5 R8.1 R24.2 U5.8 U8.8 USB.1 | length 2736
  Top Layer w6.3: D2.5 v1(1750,2950) ; U5.8 1950,2776.3 v1(1950,2640) 1950,2500.23 1972.44,2477.79 R8.1 ; R24.2 v1(3110,2180)
  Top Layer w20: 1820,2500 v1(1845,2500) ; v1(3110,2180) 3419,2180
  Top Layer w40: 3180,2180 ccw(c3160,2180) 3180,2180
  Bottom Layer w6.3: v1(1750,2950) 1750,2840 v1(1950,2640)
  Bottom Layer w20: v1(1845,2500) 1949.77,2500 v1@1950,2500.23 ; v1(1950,2500) 2270,2180 v1(3110,2180)
WDT_WDI: U2.4 U4.26 | length 1064.7
  Top Layer w6.3: U2.4 2262.6,2552.6 2440,2730 2440,3290 2361.1,3368.9 U4.26
WS2812: LED5.3 U4.12 | length 2109.6
  Top Layer w6.3: LED5.3@1705.1,2093.3 1833.3,2093.3 2460,2720 2460,3290 2492,3322 U4.12
X1_1: F2.2 X1.1 | length 429.4
  Top Layer w40: F2.2 4840,4890 5015,5065 X1.1@5135,5065
X3_1: F3.2 X3.1 | length 846.7
  Top Layer w40: F3.2 4790,4210 4870,4290 4870,4510 5031,4671 X3.1@5305,4671
pads on no net: USB.

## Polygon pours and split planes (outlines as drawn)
GND on Bottom Layer (solid): 1500,5220 4360,5250 4360,3260 4860,3260 5100,3020 5100,1500 1520,1550 1500,5220
GND on Top Layer (solid): 1530,5210 2950,5210 4360,5210 4360,3260 4860,3260 5100,3020 5100,1570 1544.49,1578.52 1530,5210

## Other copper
Top Layer:
  pour cut-out net VUSB: 1570,2620 1760,2620 1760,2280 1570,2280
  text "WARNING" at 4410,3430 h80
  text "240V AC" at 4410,3320 h80
Bottom Layer:
  pour cut-out net VUSB: 1570,2620 1760,2620 1760,2280 1570,2280

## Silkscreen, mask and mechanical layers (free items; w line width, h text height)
Top Overlay:
  rectangle: 2320,4685 2340,4775
  rectangle: 2230,4770 2340,4790
  circle w15: c1890,2950 r10
  circle w15: c3520,2450 r10
  circle w15: c3820,1995 r10
  circle w15: c1675,2780 r10
  lines w6.3 net S$1042: 1600,1970 2250,1970 ; 2248.58,1969.99 ccw(c2248.58,2081.42) 2360.01,2081.42 ; 2360,2080 2360,2680
  lines w6.3 net S$1047: 1600,1860 2245,1860 ; 2244.09,1859.98 ccw(c2244.09,2075.91) 2460.02,2075.91 ; 2460,2080 2460,2680
  text "GND" at 1875.9,4796.72 h30 r90
  text "+5V" at 1985,4796.72 h30 r90
  text "22" at 2085,4796.72 h30 r90
  text "21" at 2185,4796.72 h30 r90
  text "+3.3V" at 2291.41,4796.72 h30 r90
  text "5" at 2061.41,4520.9 h30 r270
  text "19" at 2291.41,4506.48 h30 r90
  text "15" at 1881.41,4505.12 h30 r90
  text "18" at 2191.41,4505.12 h30 r90
  text "23" at 1981.41,4492.81 h30 r90
  text "3.3V" at 2620,2280 h40
  text "USB 5V" at 2532.7,2158.2 h40
  text "5V" at 2673.13,2000 h40
  text "12V" at 2652.03,1880 h40
Top Solder:
  rectangle: 1625,1975 1735,2025
  rectangle: 1625,1805 1735,1855
  rectangle: 2305,2255 2355,2365
  rectangle: 2465,2255 2515,2365
  rectangle: 2115,1975 2225,2025
  rectangle: 2115,1805 2225,1855
  circle w40: c3160,1940 r20
  circle w40: c3160,2060 r20
  circle w40: c3160,2180 r20
  circle w40: c3160,2300 r20
  text "MES WiFi v1.4" at 2740,4250 h200
  text "g3gg0.de" at 2750,4130 h100
  text "WARNING" at 4410,3430 h80
  text "240V AC" at 4410,3320 h80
